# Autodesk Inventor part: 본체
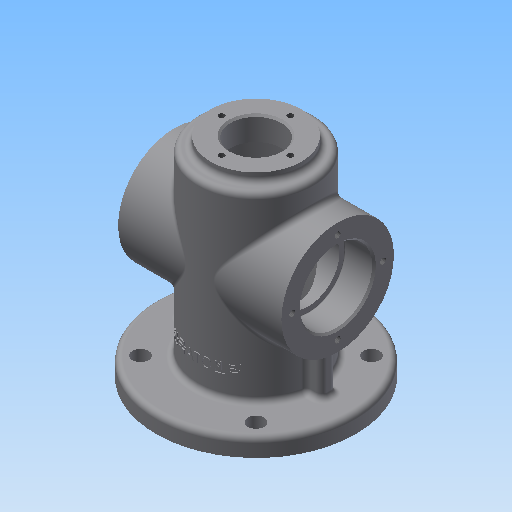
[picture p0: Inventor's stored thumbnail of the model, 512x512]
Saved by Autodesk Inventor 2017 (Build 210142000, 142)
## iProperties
Created: 2020-05
Part Number: 본체
Material: 일반
Document SubType Name: Modeling
Designer: mduedu
Density: 1 g/cm^3
Appearance: 기본값
Author: mduedu
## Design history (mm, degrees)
sketch "스케치1"
  geometry: C1 r 32 at (0, 0); 1 further point
  constraints: 1 centre point, 1 coincident
  dimensions: "d0" = 64 diameter of C1
extrude "돌출1" new body sketch "스케치1" distance "d1" = 110; taper "d2" = 0 deg
feature "쉘1" dims "d3" = 8
fillet "모깎기1" dims "d4" = 3
fillet "모깎기2" dims "d5" = 3
sketch "스케치2"
  geometry: C1 r 25 at (0, 0); 1 further point
  constraints: 1 centre point, 1 coincident
  dimensions: "d6" = 50 diameter of C1
extrude "돌출2" join sketch "스케치2" distance "d7" = 5; taper "d8" = 0 deg
sketch "스케치3"
  geometry: C1 r 14 at (0, 0); 1 further point
  constraints: 1 centre point, 1 coincident
  dimensions: "d9" = 28 diameter of C1
extrude "돌출3" cut sketch "스케치3" stored distance "d10" = 5; taper "d11" = 0 deg
fillet "모깎기3" dims "d12" = 3
sketch "스케치4"
  geometry: C1 r 32 at (0, 0) reference; C2 r 55 at (0, 0); 1 further point
  constraints: 1 centre point, 1 coincident
  dimensions: "d13" = 110 diameter of C2
extrude "돌출4" join sketch "스케치4" distance "d14" = 10; taper "d15" = 0 deg
sketch "스케치5"
  geometry: L1 (0, 0)-(-31.82, 31.82); L2 (0, 0)-(-45, 0); A1 r 45 centre (0, 0) between (-31.82, 31.82) and (-45, 0); 1 further point
  constraints: 4 end point, 2 point on circle, 1 centre point, 1 coincident, 1 horizontal
  dimensions: "d16" = 90 diameter of A1; "d71" = 45 deg angle of L1 L2
hole "구멍1" sketch "스케치5" at (-31.82, 31.82) diameter "d17" = 9; stored, may be unused: countersink angle "d21" = 90 deg, drill point angle "d23" = 118 deg; dims "d18" = 6, "d19" = 4, "d20" = 2, "d22" = 8
fillet "모깎기4" dims "d27" = 3
node "작업 평면1"
sketch "스케치6"
  geometry: L1 (0, 55)-(0, -55) reference; C1 r 31 at (-65, 0); 2 further points
  constraints: 1 centre point, 1 horizontal alignment, 1 midpoint
  dimensions: "d31" = 62 diameter of C1; "d32" = 65 distance from line of C1.centre L1
extrude "돌출5" join sketch "스케치6" stored distance "d33" = 10; taper "d34" = 0 deg
fillet "모깎기5" dims "d35" = 3
sketch "스케치7"
  geometry: C1 r 31 at (0, 0) reference; C2 r 20 at (0, 0); 1 further point
  constraints: 1 centre point, 1 coincident
  dimensions: "d36" = 40 diameter of C2
extrude "돌출6" cut sketch "스케치7" distance "d37" = 16; taper "d38" = 0 deg
sketch "스케치8"
  geometry: C1 r 20 at (0, 0) reference; C2 r 17 at (0, 0); 1 further point
  constraints: 1 centre point, 1 coincident
  dimensions: "d39" = 34 diameter of C2
extrude "돌출7" cut sketch "스케치8" stored distance "d40" = 15; taper "d41" = 0 deg
fillet "모깎기6" dims "d42" = 0.3
chamfer "모따기1" distance "d43" = 1; stored, may be unused: second distance "d44" = 2, angle "d45" = 45 deg
chamfer "모따기2" distance "d46" = 1; stored, may be unused: second distance "d47" = 2, angle "d48" = 45 deg
sketch "스케치9" dims "d49" = 50
  geometry: C1 r 31 at (0, 0) reference; 3 further points
  constraints: 2 vertical alignment, 1 coincident, 2 other
hole "구멍2" sketch "스케치9" at (0, 25) diameter "d50" = 3.242; stored, may be unused: countersink angle "d54" = 90 deg, drill point angle "d56" = 118 deg; dims "d51" = 7, "d52" = 4, "d53" = 2, "d55" = 9
sketch "스케치10" dims "d60" = 38
  geometry: 3 further points
  constraints: 2 vertical alignment, 1 coincident, 2 other
hole "구멍3" sketch "스케치10" at (0, 19) diameter "d61" = 3.242; stored, may be unused: countersink angle "d65" = 90 deg, drill point angle "d67" = 118 deg; dims "d62" = 8, "d63" = 4, "d64" = 2, "d66" = 10
sketch "스케치11"
  geometry: L1 (32, 31)-(32, 13) reference; L2 (35, 10)-(52, 10) reference; L3 (55, 7)-(55, 0) reference; L4 (55, 0)-(24, 0) reference; L5 (24, 0)-(24, 48) reference; L6 (24, 48)-(29, 48) reference; L7 (29, 48)-(29, 45.3) reference; L8 (29.3, 45)-(44, 45) reference; L9 (44, 45)-(45, 44) reference; L10 (45, 44)-(45, 41.621) reference; L11 (45, 41.621)-(36, 41.621) reference; L12 (36, 41.621)-(35.026, 40) reference; L13 (35.026, 40)-(36, 38.379) reference; L14 (36, 38.379)-(45, 38.379) reference; L15 (45, 38.379)-(45, 34) reference; L16 (45, 34)-(35, 34) reference; L17 (-32, 13)-(-32, 31) reference; L18 (-35, 34)-(-45, 34) reference; L19 (-45, 34)-(-45, 38.379) reference; L20 (-45, 38.379)-(-36, 38.379) reference; L21 (-36, 38.379)-(-35.026, 40) reference; L22 (-35.026, 40)-(-36, 41.621) reference; L23 (-36, 41.621)-(-45, 41.621) reference; L24 (-45, 41.621)-(-45, 44) reference; L25 (-45, 44)-(-44, 45) reference; L26 (-44, 45)-(-29.3, 45) reference; L27 (-29, 45.3)-(-29, 48) reference; L28 (-29, 48)-(-24, 48) reference; L29 (-24, 48)-(-24, 0) reference; L30 (-24, 0)-(-55, 0) reference; L31 (-55, 0)-(-55, 7) reference; L32 (-52, 10)-(-35, 10) reference; L33 (-25, 113)-(-25, 115) reference; L34 (-25, 115)-(-20.621, 115) reference; L35 (-20.621, 115)-(-20.621, 105) reference; L36 (-20.621, 105)-(-19, 104.026) reference; L37 (-19, 104.026)-(-17.379, 105) reference; L38 (-17.379, 105)-(-17.379, 115) reference; L39 (-17.379, 115)-(-15, 115) reference; L40 (-15, 115)-(-14, 114) reference; L41 (-14, 114)-(-14, 102) reference; L42 (-14, 102)-(-21, 102) reference; L43 (-24, 99)-(-24, 82) reference; L44 (-24, 82)-(-29, 82) reference; L45 (-29, 82)-(-29, 84.7) reference; L46 (-29.3, 85)-(-44, 85) reference; L47 (-44, 85)-(-45, 86) reference; L48 (-45, 86)-(-45, 88.379) reference; L49 (-45, 88.379)-(-36, 88.379) reference; L50 (-36, 88.379)-(-35.026, 90) reference; L51 (-35.026, 90)-(-36, 91.621) reference; L52 (-36, 91.621)-(-45, 91.621) reference; L53 (-45, 91.621)-(-45, 96) reference; L54 (-45, 96)-(-35, 96) reference; L55 (-32, 99)-(-32, 107) reference; L56 (-29, 110)-(-28, 110) reference; L57 (28, 110)-(29, 110) reference; L58 (32, 107)-(32, 99) reference; L59 (35, 96)-(45, 96) reference; L60 (45, 96)-(45, 91.621) reference; L61 (45, 91.621)-(36, 91.621) reference; L62 (36, 91.621)-(35.026, 90) reference; L63 (35.026, 90)-(36, 88.379) reference; L64 (36, 88.379)-(45, 88.379) reference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; A1 r 3 centre (35, 13) between (32, 13) and (35, 10) reference; A2 r 3 centre (52, 7) between (55, 7) and (52, 10) reference; A3 r 0.3 centre (29.3, 45.3) between (29, 45.3) and (29.3, 45) reference; A4 r 0.3 centre (-29.3, 45.3) between (-29.3, 45) and (-29, 45.3) reference; A5 r 3 centre (-52, 7) between (-52, 10) and (-55, 7) reference; A6 r 3 centre (-35, 13) between (-35, 10) and (-32, 13) reference; A7 r 3 centre (-28, 113) between (-28, 110) and (-25, 113) reference; A8 r 3 centre (-21, 99) between (-21, 102) and (-24, 99) reference; A9 r 0.3 centre (-29.3, 84.7) between (-29, 84.7) and (-29.3, 85) reference; A10 r 3 centre (-29, 107) between (-29, 110) and (-32, 107) reference; A11 r 3 centre (28, 113) between (25, 113) and (28, 110) reference; A12 r 3 centre (29, 107) between (32, 107) and (29, 110) reference; A13 r 0.3 centre (29.3, 84.7) between (29.3, 85) and (29, 84.7) reference; A14 r 3 centre (21, 99) between (24, 99) and (21, 102) reference; 1 further point
  constraints: 2 end point, 1 midpoint, 1 perpendicular, 1 point on line, 4 other
  dimensions: "d73" = 5 distance between parallel lines of L81 L19
feature "리브1" sketch "스케치11" dims "d74" = 1, "d75" = 8, "d76" = 0, "d77" = 0, "d78" = 1, "d79" = 1
fillet "모깎기7" dims "d80" = 3
fillet "모깎기8" dims "d81" = 3
node "작업 평면2"
sketch "스케치12"
  geometry: 2 further points
  constraints: 1 vertical alignment, 1 other
  dimensions: "d83" = 25 distance of point (0, 25) point (0, 0)
feature "엠보싱1" sketch "스케치12" dims "d0" = 64, "d84" = 0.5, "d85" = 0
node "솔리드1"
pattern_circular "원형 패턴1" dims angle "d25" = 360 deg
mirror "대칭1"
mirror "대칭2"
pattern_circular "원형 패턴2" dims angle "d58" = 360 deg
mirror "대칭3"
pattern_circular "원형 패턴3" dims angle "d69" = 360 deg
mirror "대칭4"
node "투영된 루프1"
node "투영된 루프2"
node "절단 모서리 투영1"
other parameters: "d30" = -45
